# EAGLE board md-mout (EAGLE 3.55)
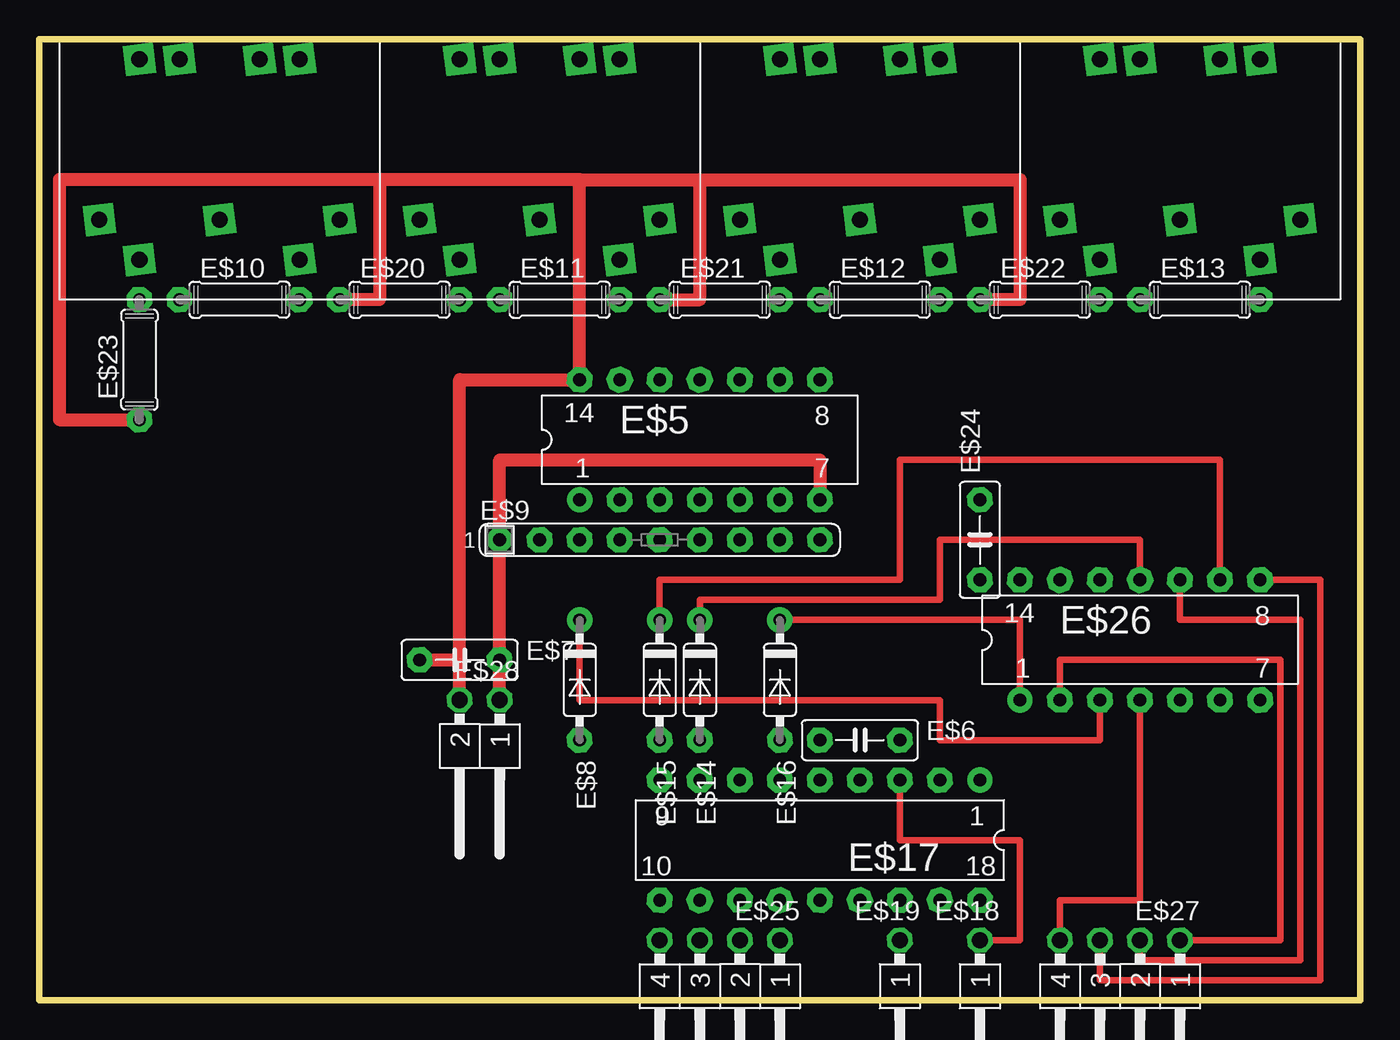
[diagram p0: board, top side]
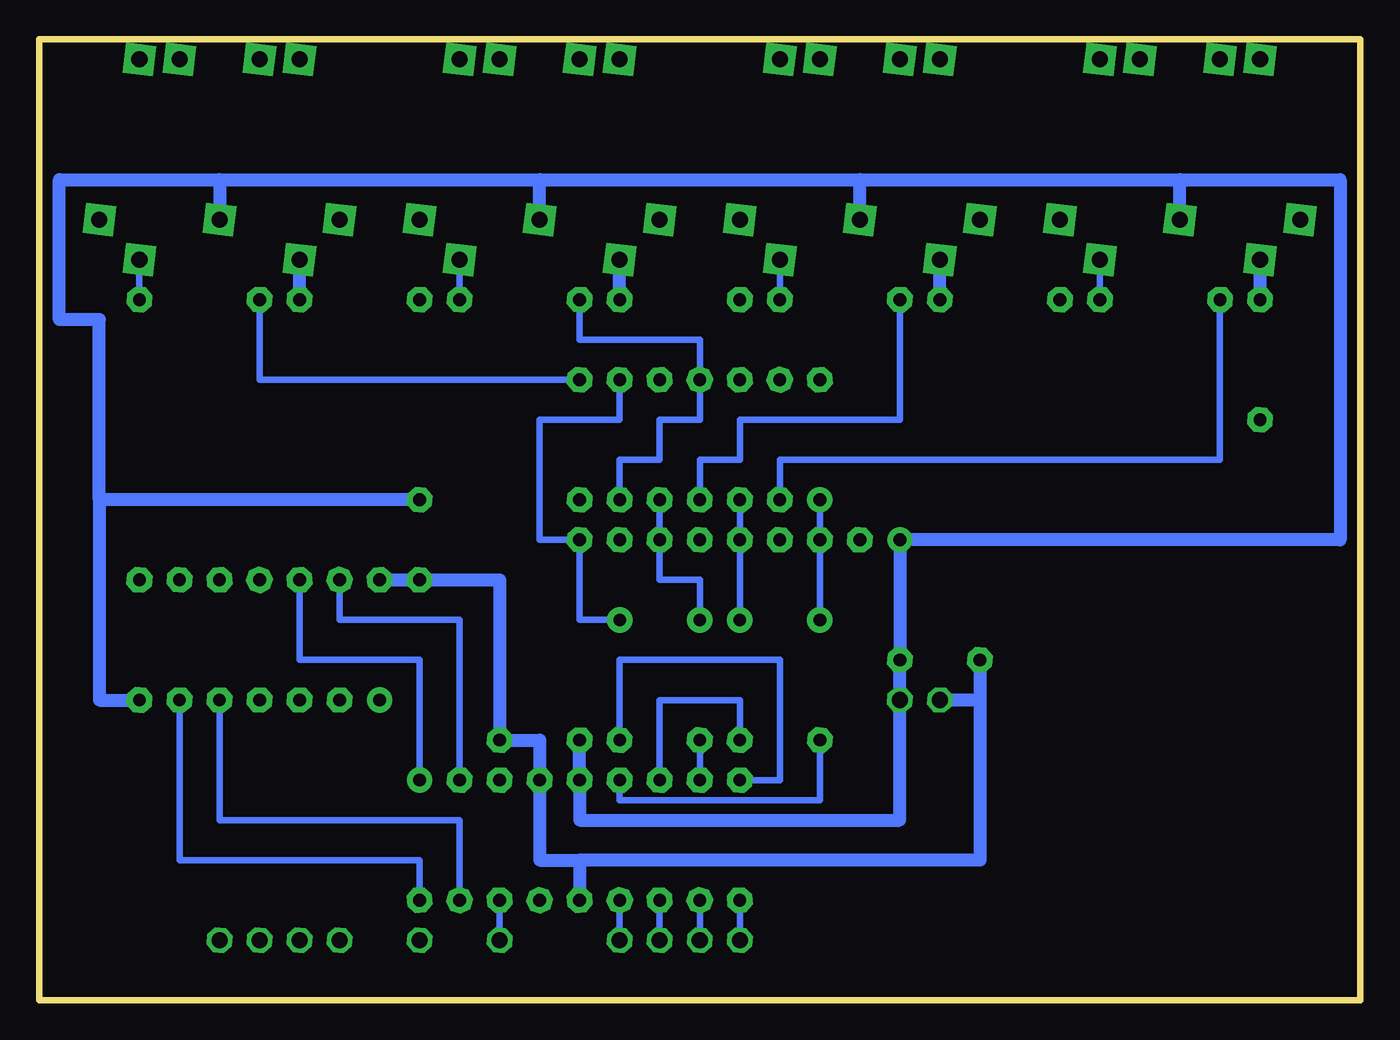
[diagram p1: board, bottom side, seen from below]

Size 83.82 x 60.96 mm. Coordinates in mm from the lower left corner, seen from the top.
Outline: 0,60.96 0,0 83.82,0 83.82,60.96 0,60.96
Copper layers used: Top, Bottom

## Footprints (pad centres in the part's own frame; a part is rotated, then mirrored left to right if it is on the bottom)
_PCB = drill 1.016 pad 1.93 square:  -7.62,10.16;  -5.08,10.16;  0,10.16;  2.54,10.16;  -2.54,0;  -7.62,-2.54;  -10.16,0;  2.54,-2.54;  5.08,0
L14 = drill 0.813 pad 1.6 round:  -7.62,-3.81 | drill 0.813 pad 1.6 octagon:  -5.08,-3.81;  -2.54,-3.81;  0,-3.81;  2.54,-3.81;  5.08,-3.81;  7.62,-3.81;  7.62,3.81;  5.08,3.81;  2.54,3.81;  0,3.81;  -2.54,3.81;  -5.08,3.81;  -7.62,3.81
B2,5 = drill 0.813 pad 1.6 octagon:  -2.54,0;  2.54,0
35-7 = drill 0.813 pad 1.6 round:  -3.81,0 | drill 0.813 pad 1.6 octagon:  3.81,0
L9 = drill 0.813 pad 1.6 round:  -10.16,0 | drill 0.813 pad 1.6 octagon:  -7.62,0;  -5.08,0;  -2.54,0;  0,0;  2.54,0;  5.08,0;  7.62,0;  10.16,0
07/7 = drill 0.813 pad 1.6 octagon:  -3.81,0;  3.81,0
L18 = drill 0.813 pad 1.6 round:  -10.16,-3.81 | drill 0.813 pad 1.6 octagon:  -7.62,-3.81;  -5.08,-3.81;  -2.54,-3.81;  0,-3.81;  2.54,-3.81;  5.08,-3.81;  7.62,-3.81;  10.16,-3.81;  10.16,3.81;  7.62,3.81;  5.08,3.81;  2.54,3.81;  0,3.81;  -2.54,3.81;  -5.08,3.81;  -7.62,3.81;  -10.16,3.81
01-1W = drill 1.016 pad 1.6 octagon:  0,0
04-1W = drill 1.016 pad 1.6 octagon:  7.62,0;  5.08,0;  2.54,0;  0,0
02-1W = drill 1.016 pad 1.6 octagon:  2.54,0;  0,0

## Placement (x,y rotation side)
E$1  DIN 5pin/180de  [_PCB]  13.97,49.53 0 top
E$2  DIN 5pin/180de  [_PCB]  34.29,49.53 0 top
E$3  DIN 5pin/180de  [_PCB]  54.61,49.53 0 top
E$4  DIN 5pin/180de  [_PCB]  74.93,49.53 0 top
E$5  74HC14  [L14]  41.91,35.56 0 top
E$6  0.1  [B2,5]  52.07,16.51 0 top
E$7  8x4k7  [B2,5]  26.67,21.59 0 top
E$8  1N4148  [35-7]  34.29,20.32 270 top
E$9  [L9]  39.37,29.21 0 top
E$10  220  [07/7]  12.7,44.45 0 top
E$11  220  [07/7]  33.02,44.45 0 top
E$12  220  [07/7]  53.34,44.45 0 top
E$13  220  [07/7]  73.66,44.45 0 top
E$14  1N4148  [35-7]  41.91,20.32 270 top
E$15  1N4148  [35-7]  39.37,20.32 270 top
E$16  1N4148  [35-7]  46.99,20.32 270 top
E$17  [L18]  49.53,10.16 180 top
E$18  [01-1W]  59.69,3.81 180 top
E$19  [01-1W]  54.61,3.81 180 top
E$20  220  [07/7]  22.86,44.45 0 top
E$21  220  [07/7]  43.18,44.45 0 top
E$22  220  [07/7]  63.5,44.45 0 top
E$23  220  [07/7]  6.35,40.64 90 top
E$24  0.1  [B2,5]  59.69,29.21 90 top
E$25  [04-1W]  46.99,3.81 180 top
E$26  4066  [L14]  69.85,22.86 0 top
E$27  [04-1W]  72.39,3.81 180 top
E$28  [02-1W]  29.21,19.05 180 top

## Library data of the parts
E$1-E$4 = con-din
E$5 E$26 = 74xx
E$6 E$7 E$24 = cap
E$8 E$14-E$16 = diode
E$9 = r-sil
E$10-E$13 E$20-E$23 = r
E$17 = pic
E$18 E$19 E$25 E$27 E$28 = con-lstb

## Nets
S$1: E$17. E$25.
S$2: E$17. E$25.
S$3: E$17. E$25.
S$4: E$17. E$25.
S$5: E$17. E$19.
S$6: E$17. E$26.
S$7: E$17. E$26.
S$8: E$17. E$26.
S$9: E$17. E$26.
S$10: E$16. E$17.
S$11: E$14. E$17.
S$12: E$8. E$17.
S$13: E$15. E$17.
S$14: E$5. E$8. E$9. E$26.
S$15: E$5. E$9. E$15. E$26.
S$16: E$5. E$9. E$14. E$26.
S$17: E$5. E$9. E$16. E$26.
S$18: E$5. E$12.
S$19: E$5. E$11.
S$20: E$2. E$20.
S$21: E$1. E$10.
S$22: E$1. E$23.
S$23: E$2. E$11.
S$24: E$3. E$21.
S$25: E$3. E$12.
S$26: E$4. E$22.
S$27: E$4. E$13.
S$28: E$5. E$13.
S$29: E$5. E$6. E$7. E$17. E$20. E$21. E$22. E$23. E$24. E$26. E$28.
S$30: E$1. E$2. E$3. E$4. E$5. E$6. E$7. E$9. E$17. E$24. E$26. E$28.
S$31: E$26. E$27.
S$32: E$26. E$27.
S$33: E$5. E$10.
S$35: E$17. E$18.
S$36: E$26. E$27.
S$37: E$26. E$27.

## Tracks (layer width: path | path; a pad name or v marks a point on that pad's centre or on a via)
S$1
  Bottom 0.406: 39.37,3.81 39.37,6.35
S$2
  Bottom 0.406: 41.91,3.81 41.91,6.35
S$3
  Bottom 0.406: 44.45,6.35 44.45,3.81
S$4
  Bottom 0.406: E$25. 46.99,6.35
S$5
  Bottom 0.406: E$19. 54.61,6.35
S$6
  Bottom 0.406: E$17. 59.69,8.89 74.93,8.89 74.93,19.05
S$7
  Bottom 0.406: 72.39,19.05 72.39,11.43 57.15,11.43 57.15,6.35
S$8
  Bottom 0.406: 59.69,13.97 59.69,21.59 67.31,21.59 67.31,26.67
S$9
  Bottom 0.406: 64.77,26.67 64.77,24.13 57.15,24.13 57.15,13.97
S$10
  Bottom 0.406: E$16. 46.99,21.59 36.83,21.59 36.83,13.97 39.37,13.97
S$11
  Bottom 0.406: 41.91,13.97 E$14.
S$12
  Bottom 0.406: E$8. 34.29,12.7 46.99,12.7 46.99,13.97
S$13
  Bottom 0.406: 44.45,13.97 44.45,19.05 39.37,19.05 E$15.
S$14
  Top 0.406: 34.29,24.13 34.29,19.05 57.15,19.05 57.15,16.51 67.31,16.51 67.31,19.05
  Bottom 0.406: 34.29,24.13 34.29,29.21 34.29,31.75
S$15
  Top 0.406: 39.37,24.13 39.37,26.67 54.61,26.67 54.61,34.29 74.93,34.29 74.93,26.67
  Bottom 0.406: 39.37,24.13 39.37,29.21 39.37,31.75
S$16
  Top 0.406: 69.85,26.67 69.85,29.21 57.15,29.21 57.15,25.4 41.91,25.4 41.91,24.13
  Bottom 0.406: 41.91,24.13 41.91,26.67 44.45,26.67 44.45,29.21 44.45,31.75
S$17
  Top 0.406: 62.23,19.05 62.23,24.13 46.99,24.13
  Bottom 0.406: 46.99,24.13 49.53,24.13 E$9. 52.07,29.21 52.07,36.83 46.99,36.83 46.99,39.37
S$18
  Bottom 0.406: 46.99,31.75 46.99,34.29 44.45,34.29 44.45,36.83 41.91,36.83 41.91,39.37 41.91,41.91 49.53,41.91 49.53,44.45
S$19
  Bottom 0.406: 41.91,31.75 41.91,34.29 39.37,34.29 39.37,36.83 29.21,36.83 29.21,44.45
S$20
  Bottom 0.813: E$20. 26.67,46.99
S$21
  Bottom 0.406: E$10. 16.51,46.99
S$22
  Bottom 0.813: E$23. 6.35,46.99
S$23
  Bottom 0.406: E$11. 36.83,46.99
S$24
  Bottom 0.813: E$21. 46.99,46.99
S$25
  Bottom 0.406: E$12. 57.15,46.99
S$26
  Bottom 0.813: E$22. 67.31,46.99
S$27
  Bottom 0.406: E$13. 77.47,46.99
S$28
  Bottom 0.406: 49.53,39.37 69.85,39.37 69.85,44.45
S$29
  Top 0.813: 26.67,19.05 26.67,21.59 | 26.67,21.59 26.67,39.37 E$5. 34.29,52.07 | 34.29,52.07 21.59,52.07 | 21.59,52.07 1.27,52.07 1.27,36.83 6.35,36.83 | 34.29,52.07 41.91,52.07 | 41.91,52.07 62.23,52.07 62.23,44.45 59.69,44.45 | 39.37,44.45 41.91,44.45 41.91,52.07 | 21.59,52.07 21.59,44.45 19.05,44.45 | 24.13,21.59 26.67,21.59
  Bottom 0.813: E$26. 59.69,26.67 54.61,26.67 E$6. 52.07,16.51 52.07,13.97 52.07,8.89 49.53,8.89 | 49.53,8.89 49.53,6.35 | 24.13,21.59 24.13,19.05 | 24.13,19.05 24.13,8.89 49.53,8.89 | 24.13,19.05 26.67,19.05
S$30
  Top 0.813: E$28. E$7. 29.21,29.21 29.21,34.29 49.53,34.29 49.53,31.75
  Bottom 0.813: 49.53,16.51 49.53,13.97 49.53,11.43 29.21,11.43 E$7. 29.21,29.21 1.27,29.21 1.27,52.07 11.43,52.07 | E$24. 80.01,31.75 | 80.01,31.75 80.01,19.05 77.47,19.05 | 80.01,31.75 80.01,43.18 82.55,43.18 82.55,52.07 72.39,52.07 | 72.39,52.07 72.39,49.53 | 72.39,52.07 52.07,52.07 | 52.07,52.07 31.75,52.07 | 31.75,52.07 11.43,52.07 | 11.43,49.53 11.43,52.07 | 31.75,49.53 31.75,52.07 | 52.07,49.53 52.07,52.07
S$31
  Top 0.406: 72.39,26.67 72.39,24.13 80.01,24.13 80.01,2.54 69.85,2.54 69.85,3.81
S$32
  Top 0.406: 67.31,3.81 67.31,1.27 81.28,1.27 81.28,26.67 77.47,26.67
S$33
  Bottom 0.406: 8.89,44.45 8.89,34.29 36.83,34.29 36.83,31.75
S$35
  Top 0.406: 54.61,13.97 54.61,10.16 62.23,10.16 62.23,3.81 E$18.
S$36
  Top 0.406: 64.77,3.81 64.77,6.35 69.85,6.35 69.85,19.05
S$37
  Top 0.406: E$27. 78.74,3.81 78.74,21.59 64.77,21.59 64.77,19.05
